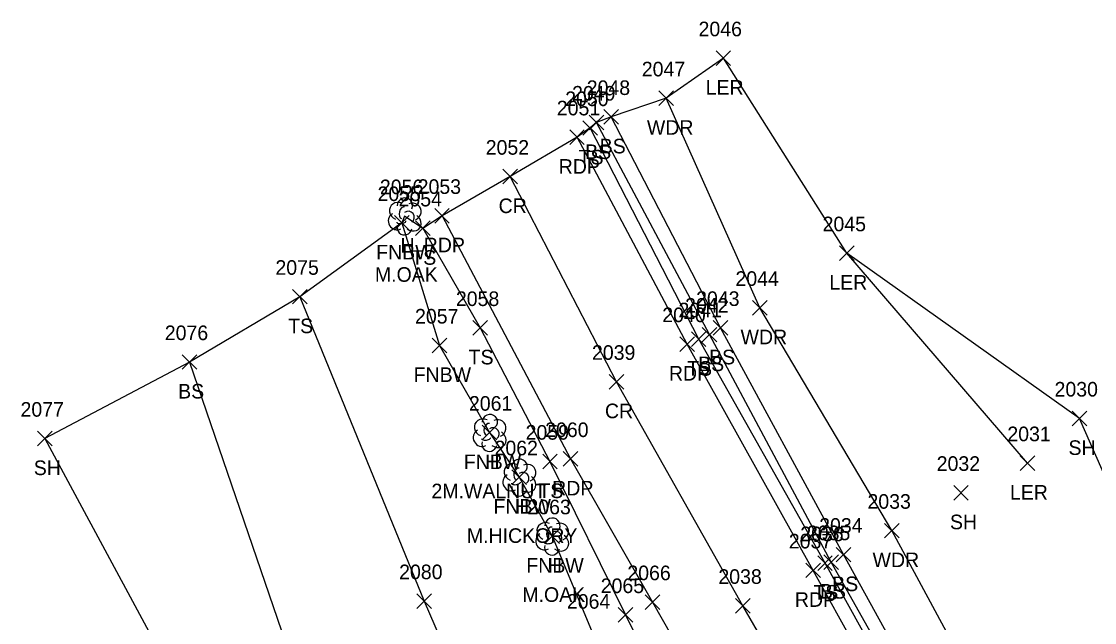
# Model space of a CAD drawing. Extents: x 1443590 to 1445966, y 578314 to 580556.
# Drawn here: x 1444691.9 to 1444839, y 579637.3 to 579719.6 of the extents above; entities that cross this region are included whole.
import ezdxf

# ---------------------------------------------------------------- set-up
doc = ezdxf.new("R2010")
doc.units = 0
for name, color, linetype in [('L_A', 7, 'Continuous'), ('L_C', 7, 'Continuous'), ('L_I', 7, 'Continuous'), ('L_TIC', 7, 'Continuous'), ('LARO', 7, 'Continuous'), ('LAWA', 7, 'Continuous'), ('LELB', 7, 'Continuous'), ('LFNC', 7, 'Continuous'), ('LSOGP', 7, 'Continuous'), ('LTD', 7, 'Continuous'), ('P_A', 7, 'Continuous'), ('P_I', 7, 'Continuous'), ('P_TIC', 7, 'Continuous'), ('PET', 7, 'Continuous'), ('PRC', 7, 'Continuous')]:
    doc.layers.add(name, color=color, linetype=linetype)

msp = doc.modelspace()

# ---------------------------------------------------------------- linework, layer by layer
at = {"layer": 'L_TIC'}
for points in [[(1444787.14, 579713.58), (1444789.14, 579715.58)], [(1444789.14, 579713.58), (1444787.14, 579715.58)], [(1444779.3, 579708.09), (1444781.3, 579710.09)], [(1444781.3, 579708.09), (1444779.3, 579710.09)], [(1444769.75, 579704.77), (1444771.75, 579706.77)], [(1444771.75, 579704.77), (1444769.75, 579706.77)], [(1444771.75, 579705.54), (1444773.75, 579707.54)], [(1444773.75, 579705.54), (1444771.75, 579707.54)], [(1444768.89, 579704.02), (1444770.89, 579706.02)], [(1444770.89, 579704.02), (1444768.89, 579706.02)], [(1444743.06, 579691.01), (1444745.06, 579693.01)], [(1444745.06, 579691.01), (1444743.06, 579693.01)], [(1444745.95, 579690.28), (1444747.95, 579692.28)], [(1444747.95, 579690.28), (1444745.95, 579692.28)], [(1444804.08, 579686.87), (1444806.08, 579688.87)], [(1444806.08, 579686.87), (1444804.08, 579688.87)], [(1444729.07, 579680.91), (1444731.07, 579682.91)], [(1444731.07, 579680.91), (1444729.07, 579682.91)], [(1444792.14, 579679.39), (1444794.14, 579681.39)], [(1444794.14, 579679.39), (1444792.14, 579681.39)], [(1444753.81, 579676.63), (1444755.81, 579678.63)], [(1444755.81, 579676.63), (1444753.81, 579678.63)], [(1444786.75, 579676.64), (1444788.75, 579678.64)], [(1444788.75, 579676.64), (1444786.75, 579678.64)], [(1444783.76, 579675.08), (1444785.76, 579677.08)], [(1444785.76, 579675.08), (1444783.76, 579677.08)], [(1444785.24, 579675.71), (1444787.24, 579677.71)], [(1444787.24, 579675.71), (1444785.24, 579677.71)], [(1444748.21, 579674.23), (1444750.21, 579676.23)], [(1444750.21, 579674.23), (1444748.21, 579676.23)], [(1444713.95, 579671.96), (1444715.95, 579673.96)], [(1444715.95, 579671.96), (1444713.95, 579673.96)], [(1444835.98, 579664.23), (1444837.98, 579666.23)], [(1444837.98, 579664.23), (1444835.98, 579666.23)], [(1444694.11, 579661.47), (1444696.11, 579663.47)], [(1444696.11, 579661.47), (1444694.11, 579663.47)], [(1444755.08, 579662.29), (1444757.08, 579664.29)], [(1444757.08, 579662.29), (1444755.08, 579664.29)], [(1444763.37, 579658.32), (1444765.37, 579660.32)], [(1444765.37, 579658.32), (1444763.37, 579660.32)], [(1444828.85, 579658.11), (1444830.85, 579660.11)], [(1444830.85, 579658.11), (1444828.85, 579660.11)], [(1444759.16, 579656.18), (1444761.16, 579658.18)], [(1444761.16, 579656.18), (1444759.16, 579658.18)], [(1444819.72, 579654.05), (1444821.72, 579656.05)], [(1444821.72, 579654.05), (1444819.72, 579656.05)], [(1444810.24, 579648.86), (1444812.24, 579650.86)], [(1444812.24, 579648.86), (1444810.24, 579650.86)], [(1444763.66, 579648.1), (1444765.66, 579650.1)], [(1444765.66, 579648.1), (1444763.66, 579650.1)], [(1444803.62, 579645.57), (1444805.62, 579647.57)], [(1444805.62, 579645.57), (1444803.62, 579647.57)], [(1444801.08, 579644.41), (1444803.08, 579646.41)], [(1444803.08, 579644.41), (1444801.08, 579646.41)], [(1444801.94, 579644.55), (1444803.94, 579646.55)], [(1444803.94, 579644.55), (1444801.94, 579646.55)], [(1444746.12, 579639.21), (1444748.12, 579641.21)], [(1444748.12, 579639.21), (1444746.12, 579641.21)], [(1444773.71, 579637.31), (1444775.71, 579639.31)], [(1444775.71, 579637.31), (1444773.71, 579639.31)]]:
    msp.add_lwpolyline(points, dxfattribs=at)
at = {"layer": 'LARO'}
msp.add_lwpolyline([(1444829.85, 579659.11), (1444805.08, 579687.87), (1444788.14, 579714.58)], dxfattribs=at)
at = {"layer": 'LAWA'}
msp.add_lwpolyline([(1445116.41, 579282.36), (1445091.57, 579273.6), (1445068.08, 579261.13), (1445063.97, 579265.77), (1445052.44, 579285.91), (1445030.61, 579313.29), (1445007.29, 579349.44), (1444981.88, 579393.33), (1444958.1, 579429.17), (1444930.43, 579469.34), (1444907.58, 579503.94), (1444877.79, 579540.6), (1444853.64, 579577.69), (1444828.42, 579618.05), (1444811.24, 579649.86), (1444793.14, 579680.39), (1444780.3, 579709.09)], dxfattribs=at)
at = {"layer": 'LELB'}
for points in [[(1445059.62, 579258.9), (1445043.89, 579279.61), (1445024.59, 579310.38), (1445003.03, 579346.49), (1444976.79, 579389.55), (1444952.41, 579425.12), (1444926.34, 579464.68), (1444902.15, 579500.76), (1444874.51, 579538.34), (1444849.34, 579574.14), (1444822.42, 579614.33), (1444804.62, 579646.57), (1444787.75, 579677.64), (1444772.75, 579706.54)], [(1445120.75, 579274.75), (1445095.98, 579262.15), (1445072.07, 579253.49), (1445056.72, 579252.73), (1445039.69, 579277.16), (1445039.13, 579277.92), (1445021.32, 579309.06), (1444999.24, 579343.98), (1444972.54, 579386.39), (1444948.75, 579423.47), (1444922.09, 579461.69), (1444897.81, 579497.23), (1444870.77, 579536.13), (1444845.96, 579571.78), (1444819.96, 579613.15), (1444802.08, 579645.41), (1444784.76, 579676.08), (1444769.89, 579705.02)], [(1445120.88, 579277.2), (1445094.09, 579267.75), (1445069.76, 579257.75), (1445059.62, 579258.9), (1445056.87, 579257.54), (1445041.61, 579277.38), (1445040.78, 579278.47), (1445023.19, 579309.75), (1445001.25, 579344.99), (1444974.42, 579387.92), (1444950.97, 579424.44), (1444924.55, 579463.55), (1444901.05, 579499.1), (1444872.7, 579536.92), (1444847.2, 579572.49), (1444820.99, 579613.47), (1444802.94, 579645.55), (1444786.24, 579676.71), (1444770.75, 579705.77)], [(1444746.95, 579691.28), (1444754.81, 579677.63), (1444764.37, 579659.32), (1444774.71, 579638.31), (1444788.05, 579611.23), (1444796.2, 579597.8), (1444819.99, 579563.54), (1444841.2, 579532.22), (1444866.71, 579495.19), (1444887.95, 579464.21), (1444910.73, 579432.04), (1444934.76, 579396.06), (1444960.57, 579355.06), (1444979.05, 579324.01)], [(1444730.07, 579681.91), (1444747.12, 579640.21), (1444759.36, 579611.87), (1444762.71, 579597.39)], [(1444714.95, 579672.96), (1444729.29, 579631.06), (1444737.35, 579609.23), (1444735.74, 579578.54)]]:
    msp.add_lwpolyline(points, dxfattribs=at)
at = {"layer": 'LFNC'}
msp.add_lwpolyline([(1444744.06, 579692.01), (1444749.21, 579675.23), (1444756.08, 579663.29), (1444760.16, 579657.18), (1444764.66, 579649.1), (1444770.08, 579636.17), (1444779.42, 579616.43), (1444782.18, 579611.85)], dxfattribs=at)
at = {"layer": 'LSOGP'}
msp.add_lwpolyline([(1444852.33, 579630.49), (1444836.98, 579665.23), (1444805.08, 579687.87), (1444788.14, 579714.58), (1444780.3, 579709.09), (1444772.75, 579706.54), (1444770.75, 579705.77), (1444769.89, 579705.02), (1444768.08, 579703.76), (1444758.9, 579698.36), (1444749.57, 579692.99), (1444746.96, 579691.27), (1444744.44, 579692.96), (1444744.06, 579692.01), (1444730.07, 579681.91), (1444714.95, 579672.96), (1444695.11, 579662.47), (1444711.89, 579631.39), (1444735.74, 579578.54), (1444738.49, 579574.77), (1444746, 579563.39), (1444751.18, 579552.76)], dxfattribs=at)
at = {"layer": 'LTD'}
for p, q in [((1444744.44, 579692.95), (1444744.44, 579692.95)), ((1444744.44, 579692.95), (1444744.44, 579692.95)), ((1444756.08, 579663.29), (1444756.08, 579663.29)), ((1444756.08, 579663.29), (1444756.08, 579663.29)), ((1444760.16, 579657.18), (1444760.16, 579657.18)), ((1444760.16, 579657.18), (1444760.16, 579657.18)), ((1444764.66, 579649.1), (1444764.66, 579649.1)), ((1444764.66, 579649.1), (1444764.66, 579649.1))]:
    msp.add_line(p, q, dxfattribs=at)
for centre in [(1444744.49, 579694.39), (1444756.13, 579664.73), (1444760.2, 579658.61), (1444764.71, 579650.54)]:
    msp.add_arc(centre, 1.05, 335.5272, 180.9563, dxfattribs=at)
for centre, major_axis, ratio, start_param, end_param in [((1444743.65, 579693.62), (1.21, -0.51), 0.895232, 1.570796, 4.712389), ((1444745.49, 579693.54), (-1.14, -0.48), 0.949671, 1.570796, 4.712389), ((1444743.36, 579692.24), (0.58, -1.04), 0.959034, 3.141593, 6.283185), ((1444744.24, 579693.41), (-0.208, -0.792), 0.645439, 3.141593, 6.283185), ((1444744.94, 579692.79), (-0.5, 0.667), 0.989748, 3.141593, 6.283185), ((1444745.44, 579692.12), (-1.09, 0.79), 0.841452, 1.570796, 4.712389), ((1444744.44, 579691.45), (0.26, 1.06), 0.942809, 1.570796, 4.712389), ((1444743.99, 579692.2), (-0.625, -0.083), 0.423636, 0, 3.141593), ((1444755.29, 579663.96), (1.21, -0.51), 0.895232, 1.570796, 4.712389), ((1444757.12, 579663.88), (-1.14, -0.48), 0.949671, 1.570796, 4.712389), ((1444755, 579662.58), (0.58, -1.04), 0.959034, 3.141593, 6.283185), ((1444755.87, 579663.75), (-0.208, -0.792), 0.645439, 3.141593, 6.283185), ((1444756.58, 579663.13), (-0.5, 0.667), 0.989748, 3.141593, 6.283185), ((1444756.08, 579661.79), (0.26, 1.06), 0.942809, 1.570796, 4.712389), ((1444755.62, 579662.54), (-0.625, -0.083), 0.423636, 0, 3.141593), ((1444757.08, 579662.46), (-1.09, 0.79), 0.841452, 1.570796, 4.712389), ((1444759.37, 579657.85), (1.21, -0.51), 0.895232, 1.570796, 4.712389), ((1444761.2, 579657.76), (-1.14, -0.48), 0.949671, 1.570796, 4.712389), ((1444759.95, 579657.64), (-0.208, -0.792), 0.645439, 3.141593, 6.283185), ((1444760.66, 579657.01), (-0.5, 0.667), 0.989748, 3.141593, 6.283185), ((1444759.07, 579656.47), (0.58, -1.04), 0.959034, 3.141593, 6.283185), ((1444759.7, 579656.43), (-0.625, -0.083), 0.423636, 0, 3.141593), ((1444761.16, 579656.35), (-1.09, 0.79), 0.841452, 1.570796, 4.712389), ((1444760.16, 579655.68), (0.26, 1.06), 0.942809, 1.570796, 4.712389), ((1444763.87, 579649.77), (1.21, -0.51), 0.895232, 1.570796, 4.712389), ((1444764.45, 579649.56), (-0.208, -0.792), 0.645439, 3.141593, 6.283185), ((1444765.7, 579649.69), (-1.14, -0.48), 0.949671, 1.570796, 4.712389), ((1444763.58, 579648.4), (0.58, -1.04), 0.959034, 3.141593, 6.283185), ((1444765.16, 579648.94), (-0.5, 0.667), 0.989748, 3.141593, 6.283185), ((1444765.66, 579648.27), (-1.09, 0.79), 0.841452, 1.570796, 4.712389), ((1444764.66, 579647.6), (0.26, 1.06), 0.942809, 1.570796, 4.712389), ((1444764.2, 579648.35), (-0.625, -0.083), 0.423636, 0, 3.141593)]:
    msp.add_ellipse(centre, major_axis=major_axis, ratio=ratio, start_param=start_param, end_param=end_param, dxfattribs=at)
at = {"layer": 'P_TIC'}
for points in [[(1444767.08, 579702.75), (1444769.08, 579704.75)], [(1444769.08, 579702.75), (1444767.08, 579704.75)], [(1444757.9, 579697.36), (1444759.9, 579699.36)], [(1444759.9, 579697.36), (1444757.9, 579699.36)], [(1444748.57, 579691.99), (1444750.57, 579693.99)], [(1444750.57, 579691.99), (1444748.57, 579693.99)], [(1444782.19, 579674.42), (1444784.19, 579676.42)], [(1444784.19, 579674.42), (1444782.19, 579676.42)], [(1444772.48, 579669.26), (1444774.48, 579671.26)], [(1444774.48, 579669.26), (1444772.48, 579671.26)], [(1444766.18, 579658.68), (1444768.18, 579660.68)], [(1444768.18, 579658.68), (1444766.18, 579660.68)], [(1444799.46, 579643.42), (1444801.46, 579645.42)], [(1444801.46, 579643.42), (1444799.46, 579645.42)], [(1444777.42, 579639.07), (1444779.42, 579641.07)], [(1444779.42, 579639.07), (1444777.42, 579641.07)], [(1444789.8, 579638.57), (1444791.8, 579640.57)], [(1444791.8, 579638.57), (1444789.8, 579640.57)]]:
    msp.add_lwpolyline(points, dxfattribs=at)
at = {"layer": 'PET'}
for points in [[(1445187.64, 579104.95), (1445149.35, 579115.57), (1445134.36, 579130.22), (1445115.96, 579155.83), (1445098.76, 579182.02), (1445071.93, 579223.13), (1445057.22, 579245.8), (1445037.84, 579275.94), (1445019.3, 579308.07), (1444997.05, 579342.56), (1444969.98, 579385.25), (1444946.15, 579421.86), (1444919.7, 579460.87), (1444895.29, 579496.39), (1444868.39, 579534.19), (1444844.21, 579570.94), (1444818.42, 579612.05), (1444800.46, 579644.42), (1444783.19, 579675.42), (1444768.08, 579703.75)], [(1444749.57, 579692.99), (1444767.18, 579659.68), (1444778.42, 579640.07), (1444792.21, 579615.83), (1444803.11, 579597.28), (1444822.86, 579565.6), (1444843.8, 579533.42), (1444869.08, 579496.25), (1444890.19, 579465.65), (1444913.09, 579433.16), (1444937.14, 579397.54), (1444963.6, 579356.94), (1444983.04, 579326.35), (1445006.82, 579289.13), (1445021.79, 579264.22), (1445044.58, 579229.01), (1445059.66, 579205.24), (1445081.95, 579172.07), (1445091.01, 579154.93), (1445104.63, 579132.07), (1445107.77, 579117.84), (1445102.26, 579109.52), (1445094.76, 579101.93)]]:
    msp.add_lwpolyline(points, dxfattribs=at)
at = {"layer": 'PRC'}
msp.add_lwpolyline([(1445134.69, 579101.81), (1445120.96, 579124.75), (1445105.7, 579149.31), (1445088.61, 579176.47), (1445062.61, 579215.94), (1445046.37, 579243.3), (1445028.61, 579272.2), (1445009.91, 579303.07), (1444988.59, 579337.21), (1444961.47, 579379.67), (1444937.03, 579417.04), (1444911.02, 579455.05), (1444885.8, 579491.61), (1444860.37, 579528.28), (1444835.41, 579566.04), (1444809.93, 579606.59), (1444790.8, 579639.57), (1444773.48, 579670.26), (1444758.9, 579698.36)], dxfattribs=at)

# ---------------------------------------------------------------- texts
at = {"layer": 'L_A'}
for s, p in [('LER', (1444785.72, 579709.58)), ('WDR', (1444777.66, 579704.09)), ('BS', (1444771.19, 579701.54)), ('TS', (1444768.3, 579700.02)), ('BS', (1444769.19, 579700.77)), ('H', (1444743.88, 579687.95)), ('FNBW', (1444740.54, 579687.01)), ('TS', (1444745.36, 579686.28)), ('LER', (1444802.67, 579682.87)), ('TS', (1444728.48, 579676.91)), ('WDR', (1444790.5, 579675.39)), ('TS', (1444753.22, 579672.63)), ('BS', (1444784.68, 579671.71)), ('BS', (1444786.19, 579672.64)), ('TS', (1444783.17, 579671.08)), ('FNBW', (1444745.68, 579670.23)), ('BS', (1444713.39, 579667.96)), ('SH', (1444835.46, 579660.23)), ('SH', (1444693.6, 579657.47)), ('FNBW', (1444752.55, 579658.29)), ('H', (1444755.51, 579658.29)), ('TS', (1444762.78, 579654.32)), ('LER', (1444827.43, 579654.11)), ('FNBW', (1444756.63, 579652.18)), ('H', (1444759.59, 579652.18)), ('SH', (1444819.21, 579650.05)), ('FNBW', (1444761.13, 579644.1)), ('H', (1444764.09, 579644.1)), ('WDR', (1444808.6, 579644.86)), ('BS', (1444803.06, 579641.57)), ('TS', (1444800.49, 579640.41)), ('BS', (1444801.38, 579640.55))]:
    msp.add_text(s, height=2, dxfattribs=at).set_placement(p)
at = {"layer": 'L_C'}
for s, p in [('M.OAK', (1444740.37, 579683.95)), ('2M.WALNUT', (1444748.12, 579654.29)), ('M.HICKORY', (1444752.98, 579648.18)), ('M.OAK', (1444760.58, 579640.1))]:
    msp.add_text(s, height=2, dxfattribs=at).set_placement(p)
at = {"layer": 'L_I'}
for s, p in [('2046', (1444784.74, 579717.58)), ('2047', (1444776.96, 579712.09)), ('2049', (1444767.4, 579708.77)), ('2048', (1444769.41, 579709.54)), ('2050', (1444766.46, 579708.02)), ('2056', (1444741.05, 579695.95)), ('2055', (1444740.73, 579695.01)), ('2054', (1444743.61, 579694.28)), ('2045', (1444801.75, 579690.87)), ('2075', (1444726.73, 579684.91)), ('2044', (1444789.8, 579683.39)), ('2058', (1444751.47, 579680.63)), ('2043', (1444784.41, 579680.64)), ('2041', (1444781.99, 579679.08)), ('2042', (1444782.9, 579679.71)), ('2057', (1444745.87, 579678.23)), ('2076', (1444711.56, 579675.96)), ('2030', (1444833.55, 579668.23)), ('2061', (1444753.26, 579666.29)), ('2061', (1444753.26, 579666.29)), ('2077', (1444691.78, 579665.47)), ('2059', (1444761.03, 579662.32)), ('2031', (1444827.08, 579662.11)), ('2062', (1444756.77, 579660.18)), ('2062', (1444756.77, 579660.18)), ('2032', (1444817.39, 579658.05)), ('2033', (1444807.9, 579652.86)), ('2063', (1444761.28, 579652.1)), ('2063', (1444761.28, 579652.1)), ('2036', (1444798.69, 579648.41)), ('2035', (1444799.6, 579648.55)), ('2034', (1444801.28, 579649.57)), ('2080', (1444743.69, 579643.21)), ('2065', (1444771.33, 579641.31)), ('2064', (1444766.69, 579639.17))]:
    msp.add_text(s, height=2, dxfattribs=at).set_placement(p)
at = {"layer": 'P_A'}
for s, p in [('RDP', (1444765.57, 579698.75)), ('CR', (1444757.33, 579693.36)), ('RDP', (1444747.06, 579687.99)), ('RDP', (1444780.68, 579670.42)), ('CR', (1444771.91, 579665.26)), ('RDP', (1444764.67, 579654.68)), ('RDP', (1444797.95, 579639.42))]:
    msp.add_text(s, height=2, dxfattribs=at).set_placement(p)
at = {"layer": 'P_I'}
for s, p in [('2051', (1444765.31, 579706.75)), ('2052', (1444755.56, 579701.36)), ('2053', (1444746.23, 579695.99)), ('2040', (1444779.77, 579678.42)), ('2039', (1444770.13, 579673.26)), ('2060', (1444763.71, 579662.68)), ('2037', (1444797.12, 579647.42)), ('2066', (1444774.98, 579643.07)), ('2038', (1444787.46, 579642.57))]:
    msp.add_text(s, height=2, dxfattribs=at).set_placement(p)

doc.saveas('drawing.dxf')
